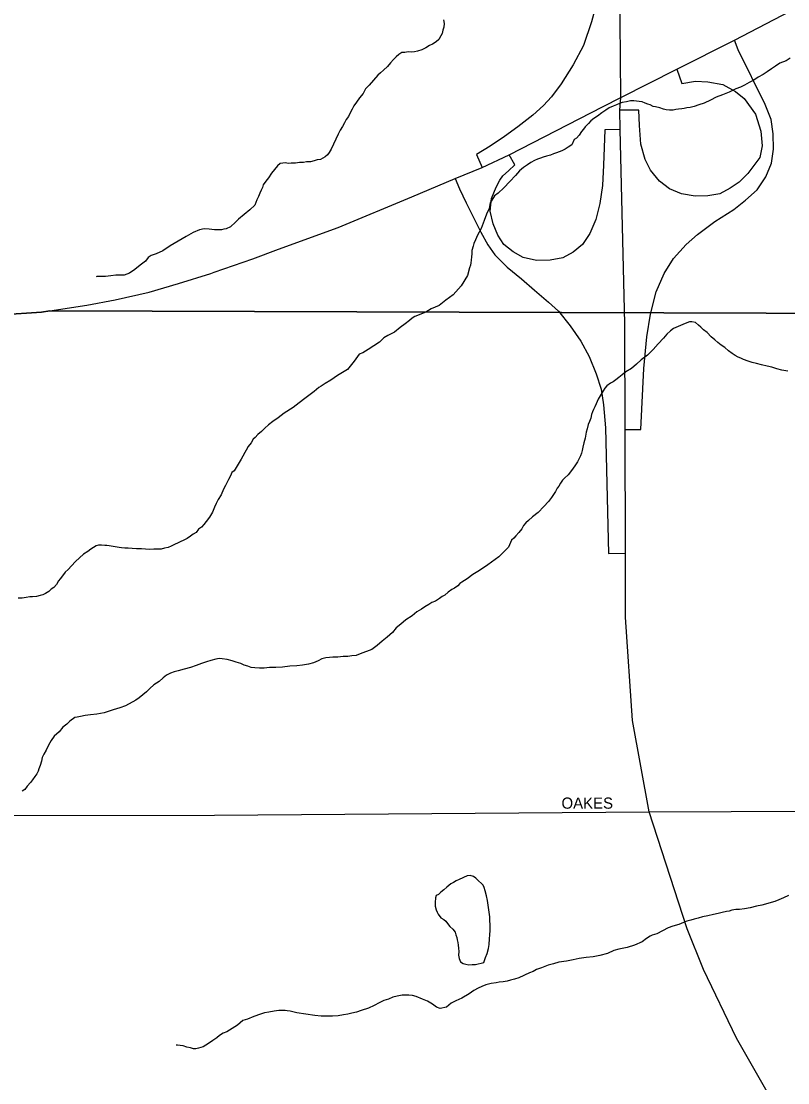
# Model space of a CAD drawing. Extents: x 2010165 to 2382125, y 1060529 to 1407316.
# Drawn here: x 2199744 to 2203170, y 1204883 to 1209626 of the extents above; entities that cross this region are included whole.
import ezdxf

# ---------------------------------------------------------------- set-up
doc = ezdxf.new("R2010")
doc.units = 0
for name, color, linetype in [('GM_X_City_Street', 7, 'Continuous'), ('GM_X_City_Street_Text', 7, 'Continuous'), ('GM_X_Corporation', 7, 'Continuous'), ('GM_X_Interchange_Ramps', 7, 'Continuous'), ('GM_X_Interstate_Route', 7, 'Continuous'), ('GM_X_Minor_Lake', 7, 'Continuous'), ('GM_X_Minor_River', 7, 'Continuous'), ('GM_X_State_Route', 7, 'Continuous')]:
    doc.layers.add(name, color=color, linetype=linetype)

msp = doc.modelspace()

# ---------------------------------------------------------------- linework, layer by layer
at = {"layer": 'GM_X_City_Street'}
msp.add_lwpolyline([(2196693.1, 1206074.3), (2200608.2, 1206079.6), (2202550.7, 1206093.1), (2205848.8, 1206107.4), (2208487.9, 1206109.2)], dxfattribs=at)
at = {"layer": 'GM_X_Corporation'}
for points in [[(2204447.2, 1221938.7), (2204662.3, 1210529.8), (2204445.3, 1208317.3), (2199872.3, 1208332.6), (2199834.9, 1208326), (2199654.4, 1208314.4), (2199497, 1208304.3), (2197215.9, 1208288.2), (2196205.1, 1208275.6), (2196632.3, 1194905.5), (2192680.8, 1194838.8), (2189318.2, 1194759.1), (2187205, 1194725.9), (2187027.1, 1208132.6), (2187013.9, 1213879), (2186978.3, 1216841.2), (2186941.3, 1219753.4), (2186933.5, 1220238.7), (2186923.4, 1220744.1), (2186878.7, 1221701)], [(2225489.9, 1195453.9), (2213202.5, 1195199), (2210879.2, 1195154.6), (2209126.8, 1195115.5), (2208833.2, 1195110.6), (2205335.3, 1195051.8), (2197309.3, 1194916.9), (2196632.3, 1194905.5), (2196205.1, 1208275.6), (2197215.9, 1208288.2), (2199497, 1208304.3), (2199654.4, 1208314.4), (2199834.9, 1208326), (2199872.3, 1208332.6), (2204445.3, 1208317.3), (2204662.3, 1210529.8), (2204447.2, 1221938.7)]]:
    msp.add_lwpolyline(points, dxfattribs=at)
at = {"layer": 'GM_X_Interchange_Ramps'}
for points in [[(2202417.6, 1209978.4), (2202340.1, 1209978.3), (2202337.6, 1209897.7), (2202329.8, 1209809.8), (2202320.3, 1209723.6), (2202293, 1209622.9), (2202256.8, 1209518.5), (2202211.5, 1209431.9), (2202157.1, 1209346.9), (2202114.4, 1209288.3), (2202079, 1209249.9), (2202030.7, 1209206.6), (2201963.8, 1209154.4), (2201904.8, 1209111.1), (2201840.8, 1209067.9), (2201779.8, 1209031.4), (2201804.2, 1208972.6)], [(2202443.3, 1207801.6), (2202513.7, 1207802.4), (2202527.1, 1208075), (2202540.3, 1208216.2), (2202556.1, 1208317.4), (2202581.4, 1208416.8), (2202618.3, 1208499.3), (2202659.3, 1208566.5), (2202715.6, 1208628.3), (2202766.5, 1208672.8), (2202843.8, 1208731), (2202928.8, 1208785.5), (2202981.6, 1208826.3), (2203034.2, 1208872.7), (2203071.6, 1208930.4), (2203097.4, 1208991.7), (2203106, 1209054.7), (2203105.1, 1209123.3), (2203096.5, 1209187.9), (2203068.9, 1209254.2), (2202949.1, 1209498.9), (2202931.8, 1209541.7)], [(2202675, 1209411.5), (2202696.9, 1209348.7), (2202757.9, 1209358.7), (2202812.5, 1209356), (2202880.8, 1209343.2), (2202936.4, 1209312.3), (2202975.5, 1209280.4), (2203025.7, 1209211.7), (2203050.2, 1209135.6), (2203056.6, 1209069.1), (2203045.7, 1209018.1), (2202991.3, 1208946.4), (2202953.7, 1208907.8), (2202912.2, 1208880.6), (2202866.8, 1208855.2), (2202813.5, 1208846.8), (2202756.4, 1208844.1), (2202695.3, 1208854.7), (2202641.6, 1208876.8), (2202597.3, 1208912.3), (2202556.6, 1208961.3), (2202533.1, 1209008.6), (2202513, 1209076.9), (2202508.1, 1209160.7), (2202505.2, 1209229.2), (2202419.7, 1209228.5)], [(2202421.7, 1209141.9), (2202352.1, 1209141.3), (2202346.6, 1208983.1), (2202342.2, 1208891.6), (2202330, 1208811.5), (2202311.9, 1208740.7), (2202286.1, 1208677.5), (2202252.5, 1208629.4), (2202211.1, 1208594.5), (2202165.7, 1208569.1), (2202108.7, 1208558.8), (2202047.7, 1208557.9), (2201988.4, 1208570.5), (2201942.3, 1208596.5), (2201901.9, 1208628.3), (2201874.6, 1208669.8), (2201852.9, 1208720.9), (2201840.7, 1208777.9), (2201846.5, 1208834.2), (2201856.2, 1208860.2), (2201866.3, 1208884.5), (2201882.7, 1208916.2), (2201897.4, 1208934.8), (2201922.3, 1208958.5), (2201950, 1208983.9), (2201924.6, 1209029.1)], [(2201683.4, 1208923.2), (2201703.1, 1208877.9), (2201733.5, 1208814.5), (2201798.2, 1208684), (2201830, 1208627), (2201861.5, 1208581.8), (2201916.6, 1208526.7), (2201979.6, 1208475.5), (2202038.6, 1208424.3), (2202101.6, 1208371.2), (2202146.2, 1208330.7), (2202198.5, 1208264.8), (2202245.2, 1208196.8), (2202282.4, 1208128.8), (2202314, 1208051.1), (2202335.9, 1207982.8), (2202346.4, 1207912.5), (2202355.5, 1207809.8), (2202369, 1207247.9), (2202444.7, 1207249.6)]]:
    msp.add_lwpolyline(points, dxfattribs=at)
at = {"layer": 'GM_X_Interstate_Route'}
for points in [[(2202421.7, 1209141.9), (2202419.7, 1209228.5), (2202423.7, 1209285.9), (2202417.6, 1209978.4), (2202417.1, 1210419.3), (2202422.4, 1210599.6), (2202425.7, 1210713.9), (2202412.8, 1211096.5), (2202389.2, 1211523.5), (2202379.6, 1212560.2), (2202369.7, 1213993.9), (2202306.1, 1215183.6), (2202266.9, 1215814.1)], [(2202442.1, 1208265.6), (2202442.1, 1208276.1), (2202421.7, 1209141.9)], [(2205851.8, 1199390.9), (2205835.5, 1199453.6), (2205745.1, 1199784.7), (2205601.4, 1200184.7), (2205452.4, 1200516.7), (2205305.7, 1200807.9), (2205045.2, 1201269.4), (2203994.2, 1203196.1), (2203302.9, 1204450.1), (2202941, 1205082.1), (2202793.8, 1205388.7), (2202720.6, 1205570.9), (2202550.7, 1206093.1), (2202476.4, 1206502.3), (2202445.4, 1206964.2), (2202444.7, 1207249.6), (2202443.3, 1207801.6), (2202442.1, 1208265.6)]]:
    msp.add_lwpolyline(points, dxfattribs=at)
at = {"layer": 'GM_X_Minor_Lake'}
for points in [[(2201779.9, 1205793.3), (2201775.8, 1205797.2), (2201765.6, 1205805), (2201751.5, 1205808.6), (2201737.4, 1205808.2), (2201701.8, 1205791.2), (2201687.9, 1205784.8), (2201676.1, 1205778.5), (2201664.2, 1205772.2), (2201646.6, 1205757.7), (2201632.9, 1205745.3), (2201619.1, 1205734.9), (2201609.3, 1205724.6), (2201599.4, 1205720.3), (2201595.7, 1205710.2), (2201594.3, 1205688), (2201594.7, 1205672), (2201599.2, 1205656), (2201603.4, 1205646.1), (2201607.7, 1205636.2), (2201620.2, 1205620.5), (2201632.4, 1205612.7), (2201642.7, 1205605), (2201648.9, 1205595.1), (2201659.3, 1205581.3), (2201673.7, 1205569.7), (2201684.1, 1205555.9), (2201686.4, 1205543.9), (2201690.8, 1205532), (2201693, 1205522), (2201695.4, 1205510), (2201697.7, 1205498), (2201698.1, 1205484), (2201700.4, 1205470), (2201698.9, 1205453.9), (2201701.3, 1205437.9), (2201707.7, 1205424), (2201720, 1205416.3), (2201732.1, 1205412.6), (2201744.2, 1205410.9), (2201760.2, 1205411.3), (2201774.2, 1205411.7), (2201812.1, 1205420.7), (2201819.5, 1205443), (2201827, 1205461.3), (2201832.4, 1205483.5), (2201836, 1205501.7), (2201837.3, 1205525.8), (2201838.8, 1205543.9), (2201840.3, 1205564), (2201839.6, 1205590.1), (2201839.1, 1205606.1), (2201838.7, 1205624.2), (2201828.2, 1205698.3)], [(2201828.2, 1205698.3), (2201824.1, 1205718.2), (2201817.5, 1205740.1), (2201813, 1205756), (2201808.8, 1205765.9), (2201779.9, 1205793.3)]]:
    msp.add_lwpolyline(points, dxfattribs=at)
at = {"layer": 'GM_X_Minor_River'}
for points in [[(2201632, 1209631.8), (2201634.4, 1209615.8), (2201632.9, 1209599.7), (2201629.2, 1209585.6), (2201625.6, 1209571.4), (2201619.9, 1209561.2), (2201610.3, 1209544.9), (2201598.5, 1209534.6), (2201582.8, 1209524.1), (2201568.9, 1209517.8), (2201553.2, 1209507.3), (2201535.3, 1209498.8), (2201515.5, 1209492.2), (2201501.5, 1209489.9), (2201487.5, 1209487.5), (2201473.4, 1209489.1), (2201459.5, 1209486.8), (2201445.4, 1209486.4), (2201431.6, 1209478), (2201419.9, 1209467.7), (2201408.2, 1209455.3), (2201394.5, 1209440.9), (2201380.9, 1209424.5), (2201363.3, 1209407.9), (2201349.6, 1209395.6), (2201337.9, 1209385.2), (2201299, 1209340), (2201283.4, 1209323.5), (2201271.9, 1209303.2), (2201256.4, 1209284.7), (2201242.9, 1209264.3), (2201231.3, 1209247.9), (2201223.7, 1209233.6), (2201214.1, 1209217.3), (2201206.5, 1209201.1), (2201196.9, 1209186.8), (2201189.2, 1209172.5), (2201179.6, 1209156.2), (2201170.1, 1209139.9), (2201160.5, 1209121.6), (2201151.1, 1209099.2), (2201139.7, 1209076.9), (2201130.3, 1209054.5), (2201120.6, 1209040.2), (2201112.9, 1209030), (2201103.1, 1209019.7), (2201081.4, 1209009.1), (2201067.4, 1209006.7), (2201053.5, 1209002.3), (2201037.5, 1208997.9), (2201019.5, 1208997.4), (2201005.5, 1208995), (2200987.5, 1208994.6), (2200969.5, 1208992.1), (2200951.5, 1208991.6), (2200937.5, 1208991.2), (2200925.4, 1208992.9), (2200913.4, 1208992.6), (2200901.4, 1208990.3), (2200889.6, 1208979.9), (2200876, 1208963.5), (2200862.5, 1208947.1), (2200849, 1208926.7)], [(2203180.6, 1209461.7), (2203162.9, 1209449.2), (2203135.2, 1209438.4), (2203115.4, 1209425.8), (2203097.7, 1209413.3), (2203078, 1209400.8), (2203060.3, 1209388.3), (2203038.6, 1209375.6), (2203018.9, 1209363.1), (2202997.1, 1209352.5), (2202977.4, 1209339.9), (2202959.6, 1209331.4), (2202937.7, 1209324.8), (2202908, 1209310), (2202878.3, 1209297.2), (2202850.5, 1209286.4), (2202824.8, 1209273.7), (2202797.1, 1209260.9), (2202773.2, 1209252.2), (2202751.4, 1209245.6), (2202733.4, 1209241.2), (2202719.5, 1209238.8), (2202707.5, 1209236.5), (2202697.5, 1209234.2), (2202681.5, 1209233.8), (2202669.5, 1209231.5), (2202657.6, 1209229.1), (2202641.5, 1209228.7), (2202627.4, 1209230.3), (2202615.3, 1209234.1), (2202599.1, 1209239.6), (2202579, 1209243.1), (2202568.9, 1209244.9), (2202554.7, 1209252.5), (2202544.5, 1209256.3), (2202532.4, 1209260), (2202520.2, 1209265.7), (2202506.1, 1209267.3), (2202494, 1209269), (2202482, 1209270.7), (2202467.9, 1209270.3), (2202450, 1209265.8)], [(2202450, 1209265.8), (2202430, 1209263.3), (2202418.1, 1209259), (2202404.3, 1209252.6), (2202390.4, 1209246.2), (2202372.5, 1209239.7), (2202356.8, 1209229.3), (2202339, 1209216.8), (2202319.4, 1209202.2), (2202303.6, 1209191.7), (2202289.9, 1209181.3), (2202280.2, 1209169), (2202264.5, 1209154.6), (2202256.8, 1209144.3), (2202249, 1209134.1), (2202237.5, 1209117.7), (2202225.8, 1209103.4), (2202216, 1209097.1), (2202204.5, 1209074.7), (2202188.8, 1209064.3), (2202175, 1209053.9), (2202161.2, 1209047.5), (2202149.2, 1209043.1), (2202137.3, 1209038.8), (2202123.4, 1209034.4), (2202109.5, 1209028.1), (2202091.6, 1209023.6), (2202077.7, 1209019.2), (2202065.8, 1209014.8), (2202051.9, 1209010.5), (2202038, 1209004.1), (2202022.2, 1208995.6), (2202006.4, 1208985.2), (2201988.7, 1208972.7), (2201971.1, 1208958.2), (2201953.6, 1208937.6), (2201928.2, 1208910.9), (2201900.9, 1208882), (2201875.5, 1208857.3), (2201859.8, 1208846.8), (2201848.3, 1208826.5), (2201840.6, 1208814.2), (2201835.2, 1208790), (2201823.9, 1208763.6), (2201812.7, 1208735.2), (2201799.6, 1208700.7), (2201784.3, 1208670.2), (2201774.9, 1208649.9), (2201767.3, 1208633.6), (2201763.6, 1208621.5), (2201758.1, 1208601.2), (2201758.5, 1208587.2), (2201756.9, 1208573.1), (2201755.3, 1208559), (2201753.6, 1208546.9), (2201751.9, 1208536.8), (2201748.2, 1208524.7), (2201739.1, 1208490.3), (2201710.3, 1208443.4), (2201675.2, 1208404.3), (2201641.8, 1208379.4), (2201612.4, 1208356.5), (2201576.7, 1208341.5), (2201553, 1208326.8), (2201503.4, 1208307.5), (2201491.6, 1208299.1), (2201479.8, 1208288.8), (2201460.2, 1208274.2), (2201438.6, 1208257.6), (2201413.1, 1208236.8), (2201383.4, 1208222), (2201365.6, 1208211.5), (2201346.1, 1208192.9), (2201320.5, 1208176.2), (2201294.8, 1208159.5), (2201271.2, 1208144.8), (2201255.3, 1208138.4), (2201232.1, 1208107.6), (2201203, 1208070.7), (2201157.6, 1208043.4), (2201128.1, 1208022.6), (2201102.4, 1208007.9), (2201084.7, 1207995.4), (2201074.9, 1207989.1), (2201053.3, 1207972.4), (2201035.6, 1207957.9), (2201012, 1207941.2), (2200986.5, 1207920.5), (2200959, 1207899.7), (2200919.5, 1207874.6), (2200892, 1207853.8), (2200868.4, 1207837.1), (2200848.8, 1207822.5), (2200833.1, 1207808.1), (2200817.5, 1207793.6), (2200801.8, 1207779.1), (2200790.1, 1207766.8), (2200780.3, 1207758.5), (2200772.7, 1207742.2), (2200759.1, 1207725.8), (2200749.5, 1207709.5)], [(2200849, 1208926.7), (2200837.3, 1208912.3), (2200825.7, 1208896), (2200822, 1208883.8), (2200816.4, 1208871.6), (2200810.7, 1208857.4), (2200805.1, 1208843.2), (2200797.5, 1208829), (2200788.1, 1208804.6), (2200766.6, 1208784), (2200715.6, 1208742.5), (2200701.9, 1208728.1), (2200680.4, 1208707.4), (2200660.6, 1208698.9), (2200650.6, 1208696.6), (2200638.7, 1208694.3), (2200626.7, 1208694), (2200608.6, 1208693.5), (2200584.5, 1208696.9), (2200562.4, 1208698.3), (2200540.4, 1208693.7), (2200512.7, 1208683), (2200481.1, 1208664.1), (2200445.6, 1208643.1), (2200410, 1208622.1), (2200376.5, 1208601.1), (2200346.8, 1208586.3), (2200325, 1208579.7), (2200311.1, 1208571.3), (2200299.6, 1208554.9), (2200276, 1208536.2), (2200252.4, 1208517.5), (2200228.8, 1208500.9), (2200205, 1208492.2), (2200185, 1208491.7), (2200166.9, 1208491.2), (2200144.9, 1208488.6), (2200120.9, 1208486), (2200098.9, 1208485.4), (2200082.9, 1208485), (2200078.9, 1208484.9)], [(2203170.4, 1208062.2), (2203144.2, 1208067.5), (2203122, 1208072.9), (2203099.7, 1208080.4), (2203077.5, 1208085.8), (2203053.3, 1208091.2), (2203031.1, 1208096.7), (2203010.9, 1208102.1), (2202992.7, 1208107.7), (2202972.4, 1208115.2), (2202960.2, 1208120.9), (2202948.1, 1208124.6), (2202935.9, 1208132.3), (2202921.6, 1208142), (2202905.2, 1208153.6), (2202888.8, 1208169.2), (2202872.5, 1208178.8), (2202858.1, 1208190.5), (2202843.8, 1208202.2), (2202827.3, 1208215.8), (2202810.8, 1208235.4), (2202794.4, 1208247), (2202782.1, 1208258.8), (2202771.8, 1208268.5), (2202757.4, 1208280.2), (2202741.3, 1208283.8), (2202731.3, 1208283.5), (2202711.4, 1208275), (2202659.9, 1208253.5), (2202646.1, 1208243.1), (2202630.5, 1208228.7), (2202614.9, 1208210.2), (2202591.5, 1208185.5), (2202568.2, 1208158.8), (2202542.8, 1208134), (2202515.3, 1208113.2), (2202493.7, 1208094.6), (2202472.2, 1208073.9), (2202446.6, 1208059.2), (2202430.9, 1208046.8), (2202415.2, 1208034.3), (2202401.4, 1208023.9), (2202389.6, 1208015.6), (2202377.7, 1208009.2), (2202362, 1207996.8), (2202352.3, 1207986.5), (2202344.6, 1207974.2), (2202337, 1207960), (2202323.5, 1207937.6), (2202314.1, 1207917.2), (2202308.4, 1207903), (2202302.7, 1207890.8), (2202297, 1207880.6), (2202293.3, 1207868.5), (2202289.7, 1207852.4), (2202284.1, 1207838.1), (2202278.5, 1207823.9), (2202273, 1207805.8), (2202269.4, 1207789.6), (2202264.1, 1207763.3), (2202258.6, 1207743.1), (2202255.1, 1207723), (2202251.5, 1207708.8), (2202247.8, 1207696.7), (2202244.1, 1207684.5), (2202238.5, 1207672.3), (2202230.8, 1207658.1), (2202219.3, 1207639.7), (2202203.8, 1207619.2), (2202188.3, 1207598.8), (2202172.7, 1207584.3), (2202162.9, 1207576), (2202155.2, 1207561.8), (2202147.5, 1207549.5), (2202139.8, 1207539.3), (2202132.2, 1207525), (2202114.8, 1207498.5), (2202101.3, 1207480), (2202079.8, 1207457.4)], [(2200749.5, 1207709.5), (2200743.8, 1207699.3), (2200734.2, 1207683), (2200726.6, 1207668.8), (2200695.9, 1207617.8), (2200686.1, 1207609.5), (2200680.4, 1207595.3), (2200670.9, 1207579), (2200665.2, 1207566.8), (2200657.5, 1207552.5), (2200648, 1207536.2), (2200638.6, 1207509.9), (2200625.2, 1207489.4), (2200615.6, 1207471.1), (2200608, 1207454.9), (2200598.6, 1207432.5), (2200585.2, 1207410.1), (2200571.6, 1207391.7), (2200560, 1207377.3), (2200550.3, 1207365), (2200536.5, 1207356.6), (2200526.9, 1207342.3), (2200513.1, 1207333.9), (2200501.3, 1207325.6), (2200485.5, 1207315.1), (2200467.7, 1207306.6), (2200457.8, 1207302.3), (2200445.9, 1207296), (2200430.1, 1207287.6), (2200414.2, 1207281.1), (2200400.4, 1207274.8), (2200384.4, 1207272.3), (2200370.5, 1207267.9), (2200354.4, 1207267.5), (2200336.4, 1207267.1), (2200318.4, 1207266.6), (2200300.3, 1207268.1), (2200282.2, 1207269.6), (2200260.1, 1207269.1), (2200240.1, 1207270.5), (2200222, 1207272.1), (2200207.9, 1207271.7), (2200191.8, 1207273.3), (2200181.8, 1207275), (2200137.5, 1207281.9), (2200127.4, 1207283.6), (2200117.4, 1207283.4), (2200103.3, 1207285), (2200089.3, 1207284.6), (2200079.3, 1207282.4), (2200055.6, 1207267.7), (2200041.9, 1207257.3), (2200022.2, 1207244.7), (2200004.6, 1207228.2), (2199987, 1207211.7), (2199969.4, 1207193.1), (2199953.8, 1207176.7), (2199940.1, 1207164.3), (2199928.5, 1207147.9), (2199918.8, 1207135.6), (2199911.1, 1207125.4), (2199901.5, 1207109.1), (2199889.8, 1207096.7), (2199878, 1207088.4), (2199868.3, 1207078.1), (2199852.5, 1207069.6), (2199840.6, 1207063.3), (2199828.6, 1207061), (2199812.7, 1207056.5), (2199794.7, 1207054.1), (2199782.7, 1207053.8), (2199766.7, 1207051.3), (2199748.7, 1207048.8), (2199730.7, 1207048.4)], [(2202079.8, 1207457.4), (2202054.5, 1207430.6), (2202028.9, 1207411.9), (2202011.3, 1207395.4), (2201999.6, 1207385), (2201989.9, 1207372.7), (2201982.3, 1207358.5), (2201968.7, 1207342), (2201955, 1207327.6), (2201945.3, 1207317.3), (2201935.5, 1207307.1), (2201922.3, 1207276.6), (2201879.4, 1207233.3), (2201830.2, 1207197.9), (2201792.8, 1207172.8), (2201763.2, 1207154), (2201737.6, 1207135.2), (2201714, 1207120.6), (2201704.1, 1207114.3), (2201696.4, 1207104), (2201680.6, 1207093.6), (2201668.7, 1207087.2), (2201653, 1207074.8), (2201637.3, 1207062.3), (2201625.5, 1207056), (2201613.7, 1207047.6), (2201596, 1207035.1), (2201580.1, 1207028.7), (2201566.3, 1207020.3), (2201548.5, 1207009.8), (2201532.8, 1206999.3), (2201513, 1206986.8), (2201491.4, 1206970.2), (2201463.9, 1206951.4), (2201440.3, 1206932.7), (2201420.7, 1206916.1), (2201403.2, 1206895.6), (2201379.7, 1206874.9), (2201358.2, 1206856.2), (2201334.6, 1206837.6), (2201311, 1206818.9), (2201259.4, 1206799.4), (2201241.6, 1206793), (2201221.6, 1206790.4), (2201203.6, 1206787.9), (2201183.6, 1206787.4), (2201159.6, 1206784.8), (2201137.5, 1206784.2), (2201121.5, 1206783.8), (2201105.5, 1206781.3), (2201087.6, 1206776.9), (2201071.8, 1206768.4), (2201050, 1206759.8), (2201028.1, 1206753.2), (2201002.1, 1206748.5), (2200976.1, 1206745.8), (2200944.1, 1206745), (2200912.1, 1206740.1), (2200882.1, 1206739.3), (2200854, 1206738.6), (2200830, 1206736), (2200810, 1206735.4), (2200787.9, 1206736.9), (2200771.8, 1206738.4), (2200757.6, 1206744.1), (2200741.4, 1206749.7), (2200725.2, 1206757.3), (2200705, 1206762.8), (2200686.8, 1206768.3), (2200664.6, 1206773.8), (2200642.4, 1206777.2), (2200628.3, 1206778.8), (2200614.4, 1206776.5), (2200592.5, 1206769.9), (2200572.6, 1206763.3), (2200550.7, 1206756.7), (2200526.9, 1206748.1), (2200501.1, 1206739.4), (2200473.2, 1206730.6), (2200445.3, 1206723.8), (2200427.4, 1206719.4), (2200411.5, 1206712.9), (2200393.7, 1206704.4), (2200378, 1206692), (2200360.4, 1206675.4), (2200336.7, 1206660.8), (2200319.2, 1206644.2), (2200303.5, 1206629.8), (2200287.8, 1206617.3), (2200272.1, 1206602.9), (2200256.4, 1206592.4), (2200210.9, 1206567.1), (2200185.1, 1206558.4), (2200155.3, 1206549.6), (2200115.5, 1206536.5), (2200081.6, 1206529.6), (2200053.6, 1206526.8), (2200029.6, 1206524.2), (2200009.7, 1206519.7), (2199993.7, 1206517.3), (2199983.8, 1206515)], [(2199983.8, 1206515), (2199962.1, 1206498.4), (2199948.4, 1206485.9), (2199930.8, 1206471.4), (2199913.3, 1206450.9), (2199891.7, 1206432.3), (2199878.3, 1206411.8), (2199866.8, 1206391.4), (2199855.4, 1206369.1), (2199845.8, 1206350.8), (2199838.2, 1206336.5), (2199834.6, 1206320.3), (2199829.1, 1206300.1), (2199823.5, 1206285.9), (2199819.8, 1206275.8), (2199814.1, 1206263.6), (2199804.4, 1206251.3), (2199794.8, 1206237), (2199785.1, 1206224.7), (2199771.5, 1206208.3), (2199759.8, 1206193.9), (2199748, 1206185.6), (2199748, 1206185.6)], [(2203173.6, 1205719.5), (2203151.8, 1205708.9), (2203130, 1205700.3), (2203112.1, 1205693.8), (2203054.5, 1205676.2), (2203030.5, 1205671.6), (2203002.6, 1205664.8), (2202976.7, 1205660.1), (2202954.7, 1205657.5), (2202938.7, 1205657.1), (2202920.7, 1205654.6), (2202908.8, 1205650.3), (2202896.8, 1205648), (2202876.9, 1205643.4), (2202858.9, 1205638.9), (2202839, 1205634.4), (2202813.1, 1205629.7), (2202789.1, 1205625.1), (2202769.3, 1205618.5), (2202751.3, 1205614), (2202737.4, 1205609.7), (2202719.5, 1205605.2), (2202703.6, 1205598.7), (2202683.8, 1205590.2), (2202655.9, 1205583.4), (2202636.1, 1205574.9), (2202610.4, 1205562.2), (2202584.6, 1205549.4), (2202564.8, 1205542.9), (2202554.8, 1205538.6), (2202539.1, 1205528.2), (2202519.4, 1205513.6), (2202485.7, 1205498.7), (2202451.9, 1205487.7), (2202416, 1205480.8), (2202392.2, 1205474.1), (2202364.4, 1205461.3), (2202330.6, 1205452.4), (2202300.7, 1205445.6), (2202268.7, 1205442.8), (2202238.7, 1205438), (2202210.8, 1205433.2), (2202180.9, 1205426.4), (2202146.9, 1205421.5)], [(2202146.9, 1205421.5), (2202123, 1205414.8), (2202099.2, 1205408.2), (2202069.4, 1205397.4), (2202047.6, 1205388.8), (2202031.7, 1205380.3), (2202015.9, 1205373.9), (2201968.3, 1205352.6), (2201948.4, 1205346), (2201930.5, 1205341.5), (2201916.6, 1205337.1), (2201898.6, 1205334.7), (2201880.6, 1205332.2), (2201866.7, 1205329.8), (2201844.7, 1205327.2), (2201820.8, 1205320.6), (2201802.9, 1205314.1), (2201787.1, 1205305.6), (2201767.3, 1205295.1), (2201745.7, 1205280.4), (2201714.1, 1205261.6), (2201686.4, 1205248.8), (2201666.6, 1205238.2), (2201645, 1205221.6), (2201617.1, 1205214.8), (2201600.9, 1205220.4), (2201582.5, 1205234), (2201560.1, 1205247.5), (2201537.8, 1205256.9), (2201509.4, 1205268.2), (2201493.2, 1205273.8), (2201477.1, 1205275.4), (2201463.1, 1205275), (2201447, 1205274.6), (2201425.1, 1205270), (2201405.2, 1205265.5), (2201385.4, 1205256.9), (2201365.5, 1205250.4), (2201343.7, 1205239.8), (2201321.9, 1205229.2), (2201296.2, 1205216.4), (2201264.4, 1205205.6), (2201242.6, 1205199), (2201222.6, 1205194.4), (2201204.7, 1205190), (2201184.7, 1205187.4), (2201160.8, 1205182.8), (2201134.8, 1205180.1), (2201110.7, 1205181.5), (2201084.6, 1205180.8), (2201056.5, 1205184.1), (2200975.9, 1205196), (2200957.8, 1205199.5), (2200945.7, 1205203.2), (2200933.6, 1205204.9), (2200923.5, 1205206.6), (2200913.5, 1205206.4), (2200895.5, 1205205.9), (2200875.5, 1205203.4), (2200851.5, 1205198.7), (2200831.5, 1205196.2), (2200813.7, 1205189.7), (2200783.9, 1205178.9), (2200756.1, 1205168.1), (2200734.2, 1205161.5), (2200710.7, 1205140.8), (2200687.1, 1205126.1), (2200663.4, 1205111.5), (2200647.5, 1205105), (2200629.8, 1205094.5), (2200618, 1205084.2), (2200600.3, 1205071.7), (2200580.6, 1205059.1), (2200556.9, 1205044.4), (2200537, 1205037.9), (2200525.1, 1205035.6), (2200515, 1205035.3), (2200500.9, 1205038.9), (2200484.8, 1205042.5), (2200468.6, 1205048.1), (2200454.5, 1205049.8), (2200442.4, 1205051.5), (2200436.4, 1205051.3)]]:
    msp.add_lwpolyline(points, dxfattribs=at)
at = {"layer": 'GM_X_State_Route'}
for points in [[(2202345.9, 1209245.8), (2202423.7, 1209285.9), (2202675, 1209411.5), (2202931.8, 1209541.7), (2203215.4, 1209689.7), (2203327.1, 1209748.5), (2204013.6, 1210143.7), (2204655.4, 1210525.8)], [(2201489.5, 1208842.2), (2201683.4, 1208923.2), (2201804.2, 1208972.6), (2201924.6, 1209029.1), (2202345.9, 1209245.8)], [(2200606.6, 1208504.5), (2200780.1, 1208565), (2200894.2, 1208607.4), (2201160.9, 1208704.8), (2201489.5, 1208842.2)], [(2199892.2, 1208335.6), (2200038.2, 1208357.4), (2200164.1, 1208381), (2200316.6, 1208415.5), (2200447.5, 1208454.8), (2200591.2, 1208499.1), (2200606.6, 1208504.5)], [(2196269.2, 1208276.5), (2196582.1, 1208280.8), (2197215.8, 1208288.2), (2199497, 1208304.3), (2199654.4, 1208314.4), (2199834.9, 1208326), (2199872.3, 1208332.7), (2199892.2, 1208335.6)]]:
    msp.add_lwpolyline(points, dxfattribs=at)

# ---------------------------------------------------------------- texts
at = {"layer": 'GM_X_City_Street_Text'}
msp.add_text('OAKES', height=50, rotation=0, dxfattribs=at).set_placement((2202159, 1206107.8))

doc.saveas('drawing.dxf')
